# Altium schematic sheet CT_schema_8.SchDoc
size 281 x 153 mm
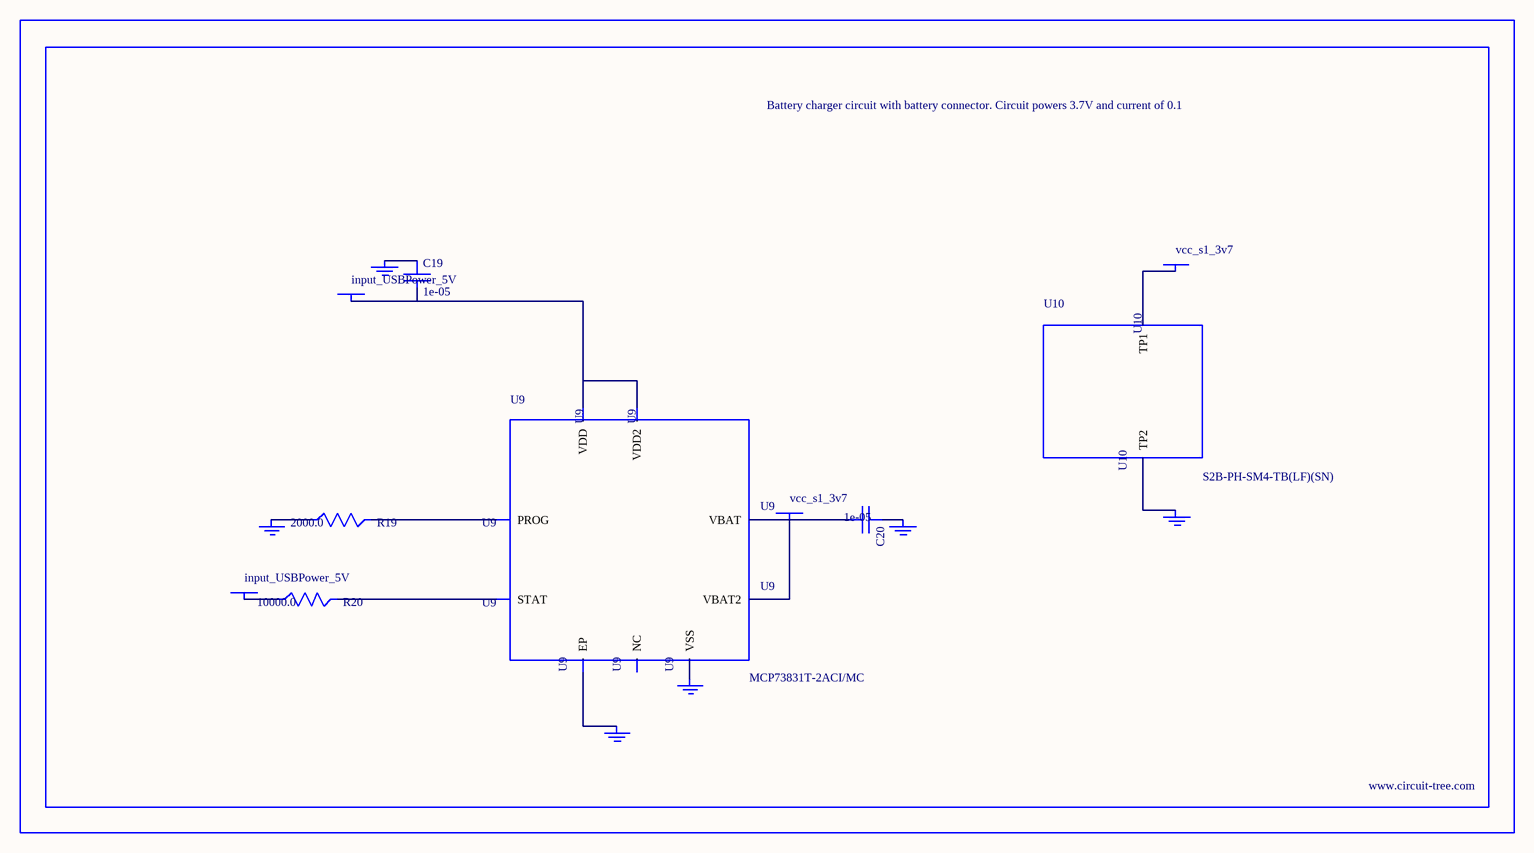
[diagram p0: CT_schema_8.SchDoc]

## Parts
BORDER7  (no value)
C19  1e-05  [C1206]
C20  1e-05  [C1206]
GND_INSTANCE_7_0  (no value)
GND_INSTANCE_7_1  (no value)
GND_INSTANCE_7_2  (no value)
GND_INSTANCE_7_3  (no value)
GND_INSTANCE_7_4  (no value)
GND_INSTANCE_7_5  (no value)
POWER_INSTANCE_7_0  input_USBPower_5V
POWER_INSTANCE_7_1  input_USBPower_5V
POWER_INSTANCE_7_2  vcc_s1_3v7
POWER_INSTANCE_7_3  vcc_s1_3v7
R19  2000.0  [R0603]
R20  10000.0  [R0603]
U9  MCP73831T-2ACI/MC  [DFN8_2X3MC]
U10  S2B-PH-SM4-TB(LF)(SN)  [JST-2-SMD]

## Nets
NetC19_1: C19.1 GND_INSTANCE_7_0.0(GND)
NetC19_2: C19.2 POWER_INSTANCE_7_0.0(PWR) U9.1(VDD) U9.2(VDD2)
NetC20_1: C20.1 GND_INSTANCE_7_1.0(GND)
NetC20_2: C20.2 POWER_INSTANCE_7_2.0(PWR) U9.3(VBAT) U9.4(VBAT2)
NetGND_INSTANCE_7_2_0: GND_INSTANCE_7_2.0(GND) R19.1
NetGND_INSTANCE_7_3_0: GND_INSTANCE_7_3.0(GND) U9.9(EP)
NetGND_INSTANCE_7_4_0: GND_INSTANCE_7_4.0(GND) U9.6(VSS)
NetGND_INSTANCE_7_5_0: GND_INSTANCE_7_5.0(GND) U10.2(TP2)
NetPOWER_INSTANCE_7_1_0: POWER_INSTANCE_7_1.0(PWR) R20.1
NetPOWER_INSTANCE_7_3_0: POWER_INSTANCE_7_3.0(PWR) U10.1(TP1)
NetR19_2: R19.2 U9.8(PROG)
NetR20_2: R20.2 U9.5(STAT)

Not connected (* = marked no-connect by the designer): U9 7(NC)

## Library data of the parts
BORDER7 = BORDER_PAGE7
C19 C20 = C1206C106K3RACTU
GND_INSTANCE_7_0-GND_INSTANCE_7_5 = GND
POWER_INSTANCE_7_0-POWER_INSTANCE_7_3 = PWR
R19 = RC0603JR-072KL
R20 = RC0603JR-0710KL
